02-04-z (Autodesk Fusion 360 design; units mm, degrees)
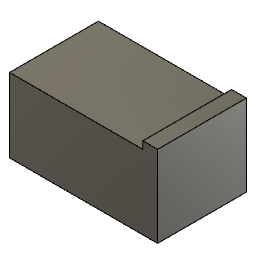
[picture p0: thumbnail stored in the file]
sketch "スケッチ1" plane through (0, 0, 0) normal (0, 0, 1) x axis (1, 0, 0)
  line L1 (-50, 25) -> (50, 25)
  line L2 (-50, -25) -> (-50, 25)
  line L3 (50, -25) -> (-50, -25)
  line L4 (50, 25) -> (50, -25)
  line L5 (-50, -25) -> (50, 25)
  line L6 (50, -25) -> (-50, 25)
  point P6 (0, 0)
  point P1 (0, 0)
  point P2 (50, 25)
  point P3 (-50, 25)
  point P5 (50, -25)
  horizontal L1
  perpendicular L1 L2
  parallel L1 L3
  parallel L2 L4
  coincident L5 P6
  coincident L6 P6
  coincident P1 P6
  dimension "d1" distance P2 P3 = 100
  dimension "d2" distance P2 P5 = 50
extrude "押し出し1" new body sketch "スケッチ1" profile of L1 L2 L3 L4 distance 60
sketch "スケッチ2" plane through (0, 25, 0) normal (0, 1, 0) x axis (-1, 0, 0)
  line L1 (50, 30) -> (50, -30)
  line L2 (-50, 30) -> (50, 30)
  line L3 (-50, -30) -> (-50, 30)
  line L4 (50, -30) -> (-50, -30)
  line L5 (-50, -30) -> (-40, -30)
  line L6 (-50, 30) -> (-50, -30)
  line L7 (-40, 30) -> (-50, 30)
  line L8 (-40, -30) -> (-40, 30)
  point P5 (-50, -30)
  point P7 (-50, -30)
  point P4 (-50, 30)
  point P8 (-50, 30)
  point P6 (-40, -30)
  horizontal L5
  vertical L6
  horizontal L7
  vertical L8
  coincident P5 P7
  coincident P4 P8
  dimension "d5" distance P6 P7 = 10
extrude "押し出し2" add sketch "スケッチ2" profile of L2 L3 L4 L5 L6 L7 L8 along normal blind 5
